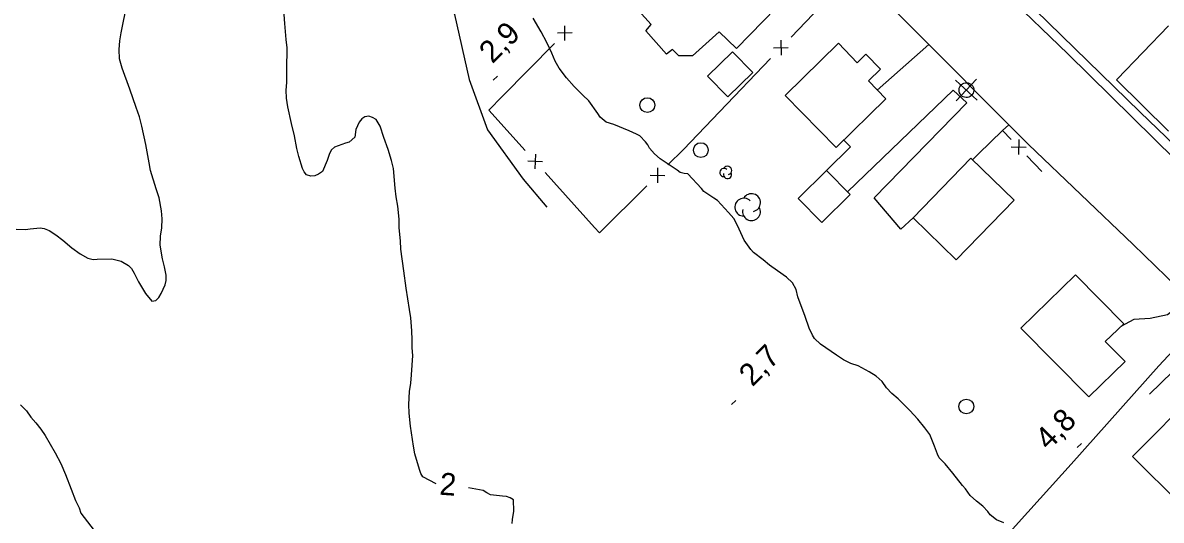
# Model space of a CAD drawing. Extents: x 381879 to 384696, y 5564785 to 5567594.
# Drawn here: x 382666 to 382820, y 5565118.6 to 5565185.9 of the extents above; entities that cross this region are included whole.
import ezdxf

# ---------------------------------------------------------------- set-up
doc = ezdxf.new("R2010")
doc.units = 0
for name, color, linetype in [('Niveau 19', 7, 'Continuous'), ('Niveau 2', 7, 'Continuous'), ('Niveau 21', 7, 'Continuous'), ('Niveau 22', 7, 'Continuous'), ('Niveau 3', 7, 'Continuous'), ('Niveau 31', 7, 'Continuous'), ('Niveau 36', 7, 'Continuous'), ('Niveau 37', 7, 'Continuous'), ('Niveau 4', 7, 'Continuous'), ('Niveau 44', 7, 'Continuous')]:
    doc.layers.add(name, color=color, linetype=linetype)

msp = doc.modelspace()

# ---------------------------------------------------------------- linework, layer by layer
at = {"layer": 'Niveau 19'}
for points in [[(382788.57, 5565182.92), (382781.58, 5565176.77)], [(382786.41, 5565159.5), (382784.75, 5565157.96), (382781.17, 5565162.23), (382793.7, 5565175.05), (382791.86, 5565176.77), (382777.53, 5565163.03)], [(382799.36, 5565172.09), (382798.51, 5565171.31)], [(382777.06, 5565170.02), (382777.94, 5565169.12), (382774.73, 5565165.89)], [(382795.27, 5565168.17), (382794.46, 5565167.35)], [(382823.68, 5565148.62), (382820.84, 5565146.39), (382818.47, 5565145.89), (382816.26, 5565145.76), (382814.49, 5565144.8)], [(382827.7, 5565144.72), (382818.38, 5565135.66)]]:
    msp.add_lwpolyline(points, dxfattribs=at)
at = {"layer": 'Niveau 2'}
for points in [[(382710.92, 5565170.43), (382710.17, 5565169.74), (382709.67, 5565169.61), (382708.18, 5565169.06), (382707.78, 5565168.69), (382707.5, 5565168.22), (382707.17, 5565167.24), (382706.54, 5565165.75), (382706.04, 5565165.41), (382705.51, 5565165.2), (382704.96, 5565165.12), (382704.4, 5565165.3), (382704.07, 5565165.72), (382703.87, 5565166.19), (382703.35, 5565167.81), (382703.1, 5565168.9), (382702.77, 5565170.59), (382702.37, 5565172.24), (382701.88, 5565174.5), (382701.71, 5565175.68), (382701.66, 5565176.76), (382701.72, 5565177.78), (382701.74, 5565179.57), (382701.76, 5565182.5), (382701.64, 5565183.61), (382701.45, 5565185.77), (382701.22, 5565188.78)], [(382798.67, 5565118.29), (382797.71, 5565118.7), (382796.85, 5565119.36), (382796.55, 5565119.8), (382795.86, 5565120.56), (382794.99, 5565121.2), (382794.15, 5565121.96), (382793.5, 5565122.9), (382793.11, 5565123.32), (382791.8, 5565124.99), (382790.74, 5565126.26), (382789.96, 5565127.08), (382789.7, 5565127.55), (382789.3, 5565128.66), (382788.68, 5565130.22), (382788.03, 5565131.12), (382787.06, 5565132.3), (382785.98, 5565133.48), (382784.39, 5565135.05), (382783.56, 5565135.76), (382782.82, 5565136.54), (382782.22, 5565137.41), (382781.42, 5565138.11), (382780.46, 5565138.71), (382779, 5565139.52), (382778.01, 5565139.84), (382777.03, 5565140.31), (382776.06, 5565140.94), (382773.88, 5565142.42), (382773.08, 5565143.18), (382772.81, 5565143.67), (382772.39, 5565144.61), (382771.81, 5565146.18), (382770.83, 5565148.81), (382770.61, 5565149.83), (382770.1, 5565150.71), (382769.31, 5565151.49), (382768.83, 5565151.8), (382766.99, 5565153.1), (382766.16, 5565153.81), (382764.84, 5565154.83), (382764.48, 5565155.21), (382763.57, 5565156.47), (382763.36, 5565157), (382762.68, 5565158.46), (382762.17, 5565159.4), (382761.46, 5565160.21), (382759.96, 5565161.86), (382759.48, 5565162.15), (382758.13, 5565163.07), (382757.79, 5565163.49), (382755.98, 5565165.45), (382755.45, 5565165.49), (382754.94, 5565165.63), (382754.52, 5565165.93), (382752.23, 5565167.47), (382751.45, 5565168.14), (382750.76, 5565168.92), (382750.55, 5565169.39), (382750.25, 5565169.8), (382749.49, 5565170.57), (382749.03, 5565170.82), (382748.02, 5565171.28), (382745.95, 5565172.11), (382744.93, 5565172.44), (382744.11, 5565173.12), (382743.79, 5565173.61), (382742.58, 5565175.34), (382741.75, 5565176.11), (382740.59, 5565177.28), (382739.57, 5565178.45), (382738.57, 5565179.73), (382738, 5565180.69), (382737.56, 5565181.75), (382736.88, 5565183.22), (382736.14, 5565184.63), (382735.06, 5565186.51)], [(382718.27, 5565133.1), (382718.25, 5565134.3), (382718.32, 5565136.04), (382718.5, 5565137.16), (382718.61, 5565138.29), (382718.77, 5565140.91), (382718.68, 5565141.95), (382718.7, 5565143.03), (382718.65, 5565144.23), (382718.51, 5565146), (382718.32, 5565147.13), (382717.87, 5565149.99), (382717.54, 5565152.33), (382717.16, 5565155.27), (382717.09, 5565156.4), (382716.93, 5565158.14), (382716.93, 5565159.34), (382716.76, 5565161.1), (382716.5, 5565162.35), (382716.4, 5565163.53), (382716.16, 5565166.18), (382715.89, 5565167.24), (382715.42, 5565168.74), (382714.86, 5565170.35), (382714.37, 5565171.92), (382713.81, 5565172.79), (382713.33, 5565173.08), (382712.81, 5565173.26), (382712.3, 5565173.15), (382711.87, 5565172.88), (382711.52, 5565172.45), (382711.08, 5565171.44), (382710.92, 5565170.43)], [(382665.74, 5565134.24), (382666.55, 5565133.44), (382667.14, 5565132.59), (382667.81, 5565131.82), (382668.49, 5565130.93), (382669.04, 5565130.07), (382670.42, 5565127.76), (382671.16, 5565126.31), (382671.8, 5565124.83), (382672.59, 5565122.85), (382673.16, 5565121.29), (382673.64, 5565120.3), (382673.9, 5565119.59)], [(382721.94, 5565123.54), (382720.12, 5565124.51), (382719.86, 5565124.95), (382719.67, 5565125.5), (382719.04, 5565127.6), (382718.87, 5565128.64), (382718.44, 5565131.37), (382718.27, 5565133.1)], [(382732.22, 5565118.21), (382732.23, 5565118.72), (382732.42, 5565119.85), (382732.4, 5565121.39), (382731.93, 5565121.68), (382731.44, 5565121.85), (382730.9, 5565121.89), (382729.27, 5565122.08), (382728.76, 5565122.32), (382728.3, 5565122.66), (382726.3, 5565123.03)], [(382673.9, 5565119.59), (382675.67, 5565117.27)]]:
    msp.add_lwpolyline(points, dxfattribs=at)
at = {"layer": 'Niveau 21'}
for points in [[(382707.89, 5565289.64), (382710.87, 5565282.99), (382715.11, 5565275.53), (382722.05, 5565265.61), (382731.75, 5565251.62), (382745.74, 5565231.67), (382755.76, 5565217.24), (382762.3, 5565209.34), (382772.65, 5565198.57), (382785.13, 5565186.38), (382802.03, 5565169.4), (382816.2, 5565155.9)], [(382824.8, 5565164.5), (382807.34, 5565181.68), (382782.33, 5565205.76), (382775.2, 5565212.91), (382770.11, 5565218.27), (382766.65, 5565222.52), (382755.84, 5565237.66), (382740.99, 5565259.24), (382725.12, 5565282.01), (382720.5, 5565290.39)], [(382823.6, 5565148.7), (382816.2, 5565155.9)]]:
    msp.add_lwpolyline(points, dxfattribs=at)
at = {"layer": 'Niveau 22'}
for points in [[(382834.65, 5565156.92), (382817.13, 5565173.77), (382779.9, 5565210.11), (382774.91, 5565215.1), (382769.87, 5565220.59), (382762.75, 5565230.09), (382752.56, 5565244.68), (382735.46, 5565269.21), (382729.59, 5565277.68), (382723.47, 5565287.47), (382720.14, 5565294.97)], [(382671.57, 5565291.49), (382676.09, 5565281.36), (382680.78, 5565271.24), (382685.95, 5565257.95), (382690, 5565247.09), (382695.65, 5565236.75), (382702.39, 5565227.01), (382709.28, 5565217.47), (382715.61, 5565208.12), (382720.6, 5565197.91), (382724.4, 5565186.98), (382726.37, 5565178.2), (382728.85, 5565171.39), (382733.7, 5565164.73), (382736.9, 5565160.94)], [(382825.38, 5565145.62), (382819.66, 5565139.5), (382807.78, 5565126.23), (382800.69, 5565118.32), (382796.32, 5565113.46), (382789.86, 5565104.41), (382784.09, 5565097.15), (382781.22, 5565093.24), (382772.47, 5565081.79), (382766.54, 5565072.04), (382763.79, 5565066.25), (382762.4, 5565063.74)]]:
    msp.add_lwpolyline(points, dxfattribs=at)
at = {"layer": 'Niveau 3'}
for p, q in [((382729.64, 5565178.1), (382730.21, 5565178.67)), ((382761.88, 5565134.27), (382762.45, 5565134.84)), ((382808.61, 5565128.45), (382809.18, 5565129.02))]:
    msp.add_line(p, q, dxfattribs=at)
at = {"layer": 'Niveau 31'}
for points in [[(382769.73, 5565189.8), (382762.53, 5565182.39), (382760.2, 5565184.63), (382756.61, 5565181.41), (382754.74, 5565181.39), (382753.89, 5565182.27), (382753.07, 5565181.61), (382750.3, 5565184.76), (382751.01, 5565185.63), (382749.29, 5565187.54), (382753.5, 5565191.64), (382755.86, 5565189.61), (382762.11, 5565196.35), (382764.11, 5565194.25), (382765.98, 5565195.29), (382767.27, 5565193.98), (382767.47, 5565191.98)], [(382776.02, 5565169), (382769.12, 5565176.05), (382776.32, 5565183.1), (382778.88, 5565180.48), (382780.04, 5565181.62), (382782.01, 5565179.61), (382780.37, 5565178.01), (382782.75, 5565175.57)], [(382758.63, 5565178.66), (382762.01, 5565181.95), (382764.73, 5565179.15), (382761.35, 5565175.86)], [(382786.41, 5565159.5), (382794.24, 5565167.56), (382800.08, 5565161.89), (382792.25, 5565153.83)], [(382777.91, 5565162.64), (382774.08, 5565158.89), (382770.9, 5565162.14), (382774.73, 5565165.89)], [(382810.2, 5565135.3), (382815.1, 5565140.1), (382812.4, 5565142.8), (382814.9, 5565145.2), (382808.4, 5565151.8), (382801, 5565144.6)], [(382816.09, 5565127.26), (382824.86, 5565136.1), (382831.4, 5565129.6), (382822.62, 5565120.76)]]:
    msp.add_lwpolyline(points, close=True, dxfattribs=at)
at = {"layer": 'Niveau 36'}
for p, q in [((382792.16, 5565178.13), (382795.07, 5565175.41)), ((382792.26, 5565175.32), (382794.98, 5565178.23))]:
    msp.add_line(p, q, dxfattribs=at)
for centre in [(382750.49, 5565174.74), (382757.72, 5565168.66), (382793.62, 5565134.01)]:
    msp.add_circle(centre, 1, dxfattribs=at)
msp.add_ellipse((382793.63, 5565176.77), major_axis=(-0.048, -0.999), ratio=0.999982, dxfattribs=at)
at = {"layer": 'Niveau 37'}
for p, q in [((382740.33, 5565184.49), (382738.33, 5565184.47)), ((382739.34, 5565183.48), (382739.33, 5565185.48)), ((382768.53, 5565183.5), (382768.57, 5565181.49)), ((382767.55, 5565182.47), (382769.55, 5565182.52)), ((382799.69, 5565169.11), (382801.69, 5565169.08)), ((382800.7, 5565170.1), (382800.67, 5565168.09)), ((382735.36, 5565168.12), (382735.26, 5565166.12)), ((382736.31, 5565167.07), (382734.31, 5565167.17)), ((382751.86, 5565166.26), (382751.85, 5565164.26)), ((382750.85, 5565165.26), (382752.85, 5565165.25))]:
    msp.add_line(p, q, dxfattribs=at)
for points in [[(382776.85, 5565191.16), (382769.93, 5565183.94)], [(382820.95, 5565185.48), (382814.03, 5565178.27)], [(382730.9, 5565175.94), (382737.93, 5565183.06)], [(382767.16, 5565181.05), (382760.25, 5565173.83)], [(382814.03, 5565178.27), (382813.94, 5565178.17), (382820.96, 5565171.23)], [(382733.97, 5565168.61), (382729.04, 5565174.06), (382730.9, 5565175.94)], [(382760.25, 5565173.83), (382755.38, 5565168.75), (382753.27, 5565166.66)], [(382799.68, 5565170.09), (382798.51, 5565171.31), (382795.26, 5565168.18)], [(382803.84, 5565165.78), (382801.82, 5565167.87)], [(382743.36, 5565158.22), (382736.65, 5565165.64)], [(382750.43, 5565163.85), (382744.01, 5565157.5), (382743.36, 5565158.22)]]:
    msp.add_lwpolyline(points, dxfattribs=at)
at = {"layer": 'Niveau 4'}
msp.add_lwpolyline([(382665.14, 5565157.99), (382666.4, 5565157.92), (382667.03, 5565158.03), (382668.36, 5565158.16), (382668.93, 5565158.08), (382669.6, 5565157.78), (382670.52, 5565157.19), (382671.45, 5565156.49), (382672.68, 5565155.47), (382673.79, 5565154.63), (382674.85, 5565154.05), (382675.57, 5565153.89), (382676.07, 5565153.92), (382678.08, 5565153.97), (382679.32, 5565153.64), (382680.34, 5565153.06), (382680.72, 5565152.66), (382681.1, 5565152.05), (382681.68, 5565150.87), (382682.62, 5565149.26), (382683.47, 5565148.24), (382684.02, 5565148.32), (382684.43, 5565148.76), (382684.74, 5565149.29), (382685.29, 5565150.47), (382685.41, 5565151.03), (382685.4, 5565151.74), (382685.2, 5565152.88), (382684.91, 5565153.98), (382684.62, 5565155.83), (382684.67, 5565157.02), (382684.83, 5565158.17), (382684.89, 5565159.36), (382684.79, 5565160.47), (382684.48, 5565162.19), (382684.08, 5565163.43), (382683.32, 5565165.91), (382683.1, 5565166.96), (382682.65, 5565169.44), (382682.14, 5565171.89), (382681.81, 5565173.17), (382681.38, 5565174.43), (382680.51, 5565176.89), (382679.48, 5565179.73), (382679.13, 5565181.01), (382679.07, 5565182.28), (382679.15, 5565183.44), (382679.32, 5565184.52), (382679.57, 5565185.62), (382679.9, 5565187.41)], dxfattribs=at)
at = {"layer": 'Niveau 44'}
for centre, radius, start, end in [((382760.85, 5565165.64), 0.56, 44.1153, 269.8039), ((382761.33, 5565165.92), 0.56, 282.2692, 149.7262), ((382761.33, 5565165.36), 0.56, 166.9368, 29.6212), ((382763.53, 5565160.95), 1.21, 44.1153, 269.8039), ((382764.57, 5565161.56), 1.21, 282.2692, 149.7262), ((382764.57, 5565160.35), 1.21, 166.9368, 29.6212)]:
    msp.add_arc(centre, radius, start, end, dxfattribs=at)

# ---------------------------------------------------------------- texts
at = {"layer": 'Niveau 2'}
msp.add_text('2', height=3, rotation=355.8212, dxfattribs=at).set_placement((382722.31, 5565122.1))
at = {"layer": 'Niveau 3'}
for s, p in [('2,9', (382729.54, 5565180.24)), ('2,7', (382764.68, 5565136.59)), ('4,8', (382804.73, 5565127.97))]:
    msp.add_text(s, height=3, rotation=44.7717, dxfattribs=at).set_placement(p)

doc.saveas('drawing.dxf')
